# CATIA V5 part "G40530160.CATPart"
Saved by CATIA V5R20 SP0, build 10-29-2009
Part number: G40530160
Revision: 6
Definition: design
Nomenclature: G40530160
Source: made
Description: NOT SPECIFIED
Bounding box of the stored display mesh (mm): x -80 to 80, y -12.5 to 12.5, z -30 to 0
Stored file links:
  C:\Users\Raffaele\Desktop\3D X SITO CF\BOLEX\29-GUIDE STRIP REF 405\G40530160.CATPart
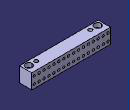
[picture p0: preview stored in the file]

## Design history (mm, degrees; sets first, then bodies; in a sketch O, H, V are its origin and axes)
Body1 "MANIFOLD_SOLID_BREP #5494" (main body)
  Solid1: solid without history
Body2 "MANIFOLD_SOLID_BREP #5632"
  Solid2: solid without history
Body3 "MANIFOLD_SOLID_BREP #5744"
  Solid3: solid without history
Body4 "MANIFOLD_SOLID_BREP #5856"
  Solid4: solid without history
Body5 "MANIFOLD_SOLID_BREP #5968"
  Solid5: solid without history
Body6 "MANIFOLD_SOLID_BREP #6080"
  Solid6: solid without history
Body7 "MANIFOLD_SOLID_BREP #6192"
  Solid7: solid without history
Body8 "MANIFOLD_SOLID_BREP #6304"
  Solid8: solid without history
Body9 "MANIFOLD_SOLID_BREP #6416"
  Solid9: solid without history
Body10 "MANIFOLD_SOLID_BREP #6528"
  Solid10: solid without history
Body11 "MANIFOLD_SOLID_BREP #6640"
  Solid11: solid without history
Body12 "MANIFOLD_SOLID_BREP #6752"
  Solid12: solid without history
Body13 "MANIFOLD_SOLID_BREP #6890"
  Solid13: solid without history
Body14 "MANIFOLD_SOLID_BREP #7028"
  Solid14: solid without history
Body15 "MANIFOLD_SOLID_BREP #7166"
  Solid15: solid without history
Body16 "MANIFOLD_SOLID_BREP #7304"
  Solid16: solid without history
Body17 "MANIFOLD_SOLID_BREP #7442"
  Solid17: solid without history
Body18 "MANIFOLD_SOLID_BREP #7580"
  Solid18: solid without history
Body19 "MANIFOLD_SOLID_BREP #7718"
  Solid19: solid without history
Body20 "MANIFOLD_SOLID_BREP #7856"
  Solid20: solid without history
Body21 "MANIFOLD_SOLID_BREP #7968"
  Solid21: solid without history
Body22 "MANIFOLD_SOLID_BREP #8080"
  Solid22: solid without history
Body23 "MANIFOLD_SOLID_BREP #8192"
  Solid23: solid without history
Body24 "MANIFOLD_SOLID_BREP #8304"
  Solid24: solid without history
Body25 "MANIFOLD_SOLID_BREP #8416"
  Solid25: solid without history
Body26 "MANIFOLD_SOLID_BREP #8528"
  Solid26: solid without history
Body27 "MANIFOLD_SOLID_BREP #8640"
  Solid27: solid without history
Body28 "MANIFOLD_SOLID_BREP #8752"
  Solid28: solid without history
Body29 "MANIFOLD_SOLID_BREP #8864"
  Solid29: solid without history
Body30 "MANIFOLD_SOLID_BREP #8976"
  Solid30: solid without history
Body31 "MANIFOLD_SOLID_BREP #9114"
  Solid31: solid without history
Body32 "MANIFOLD_SOLID_BREP #9252"
  Solid32: solid without history
Body33 "MANIFOLD_SOLID_BREP #9390"
  Solid33: solid without history
Body34 "MANIFOLD_SOLID_BREP #9528"
  Solid34: solid without history
Body35 "MANIFOLD_SOLID_BREP #9666"
  Solid35: solid without history
Body36 "MANIFOLD_SOLID_BREP #9804"
  Solid36: solid without history
Body37 "MANIFOLD_SOLID_BREP #9916"
  Solid37: solid without history
Body38 "MANIFOLD_SOLID_BREP #10028"
  Solid38: solid without history
Body39 "MANIFOLD_SOLID_BREP #10140"
  Solid39: solid without history
Body40 "MANIFOLD_SOLID_BREP #10252"
  Solid40: solid without history
Body41 "MANIFOLD_SOLID_BREP #10364"
  Solid41: solid without history
Body42 "MANIFOLD_SOLID_BREP #10476"
  Solid42: solid without history
Body43 "MANIFOLD_SOLID_BREP #10588"
  Solid43: solid without history
Body44 "MANIFOLD_SOLID_BREP #10700"
  Solid44: solid without history
Body45 "MANIFOLD_SOLID_BREP #10812"
  Solid45: solid without history
Body46 "MANIFOLD_SOLID_BREP #10924"
  Solid46: solid without history
Body47 "MANIFOLD_SOLID_BREP #11036"
  Solid47: solid without history
Body48 "MANIFOLD_SOLID_BREP #11148"
  Solid48: solid without history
